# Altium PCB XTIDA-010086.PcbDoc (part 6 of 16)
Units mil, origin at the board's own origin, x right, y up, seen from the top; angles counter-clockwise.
Board outline 14763.78 x 8267.72 mil, 6 copper layers (Top Layer, GND Layer, Signal Layer 1, Signal Layer 2, Power Layer, Bottom Layer), stack 62 mil thick; 1933 components, 1002 nets, 4886 pads, 6482 vias.
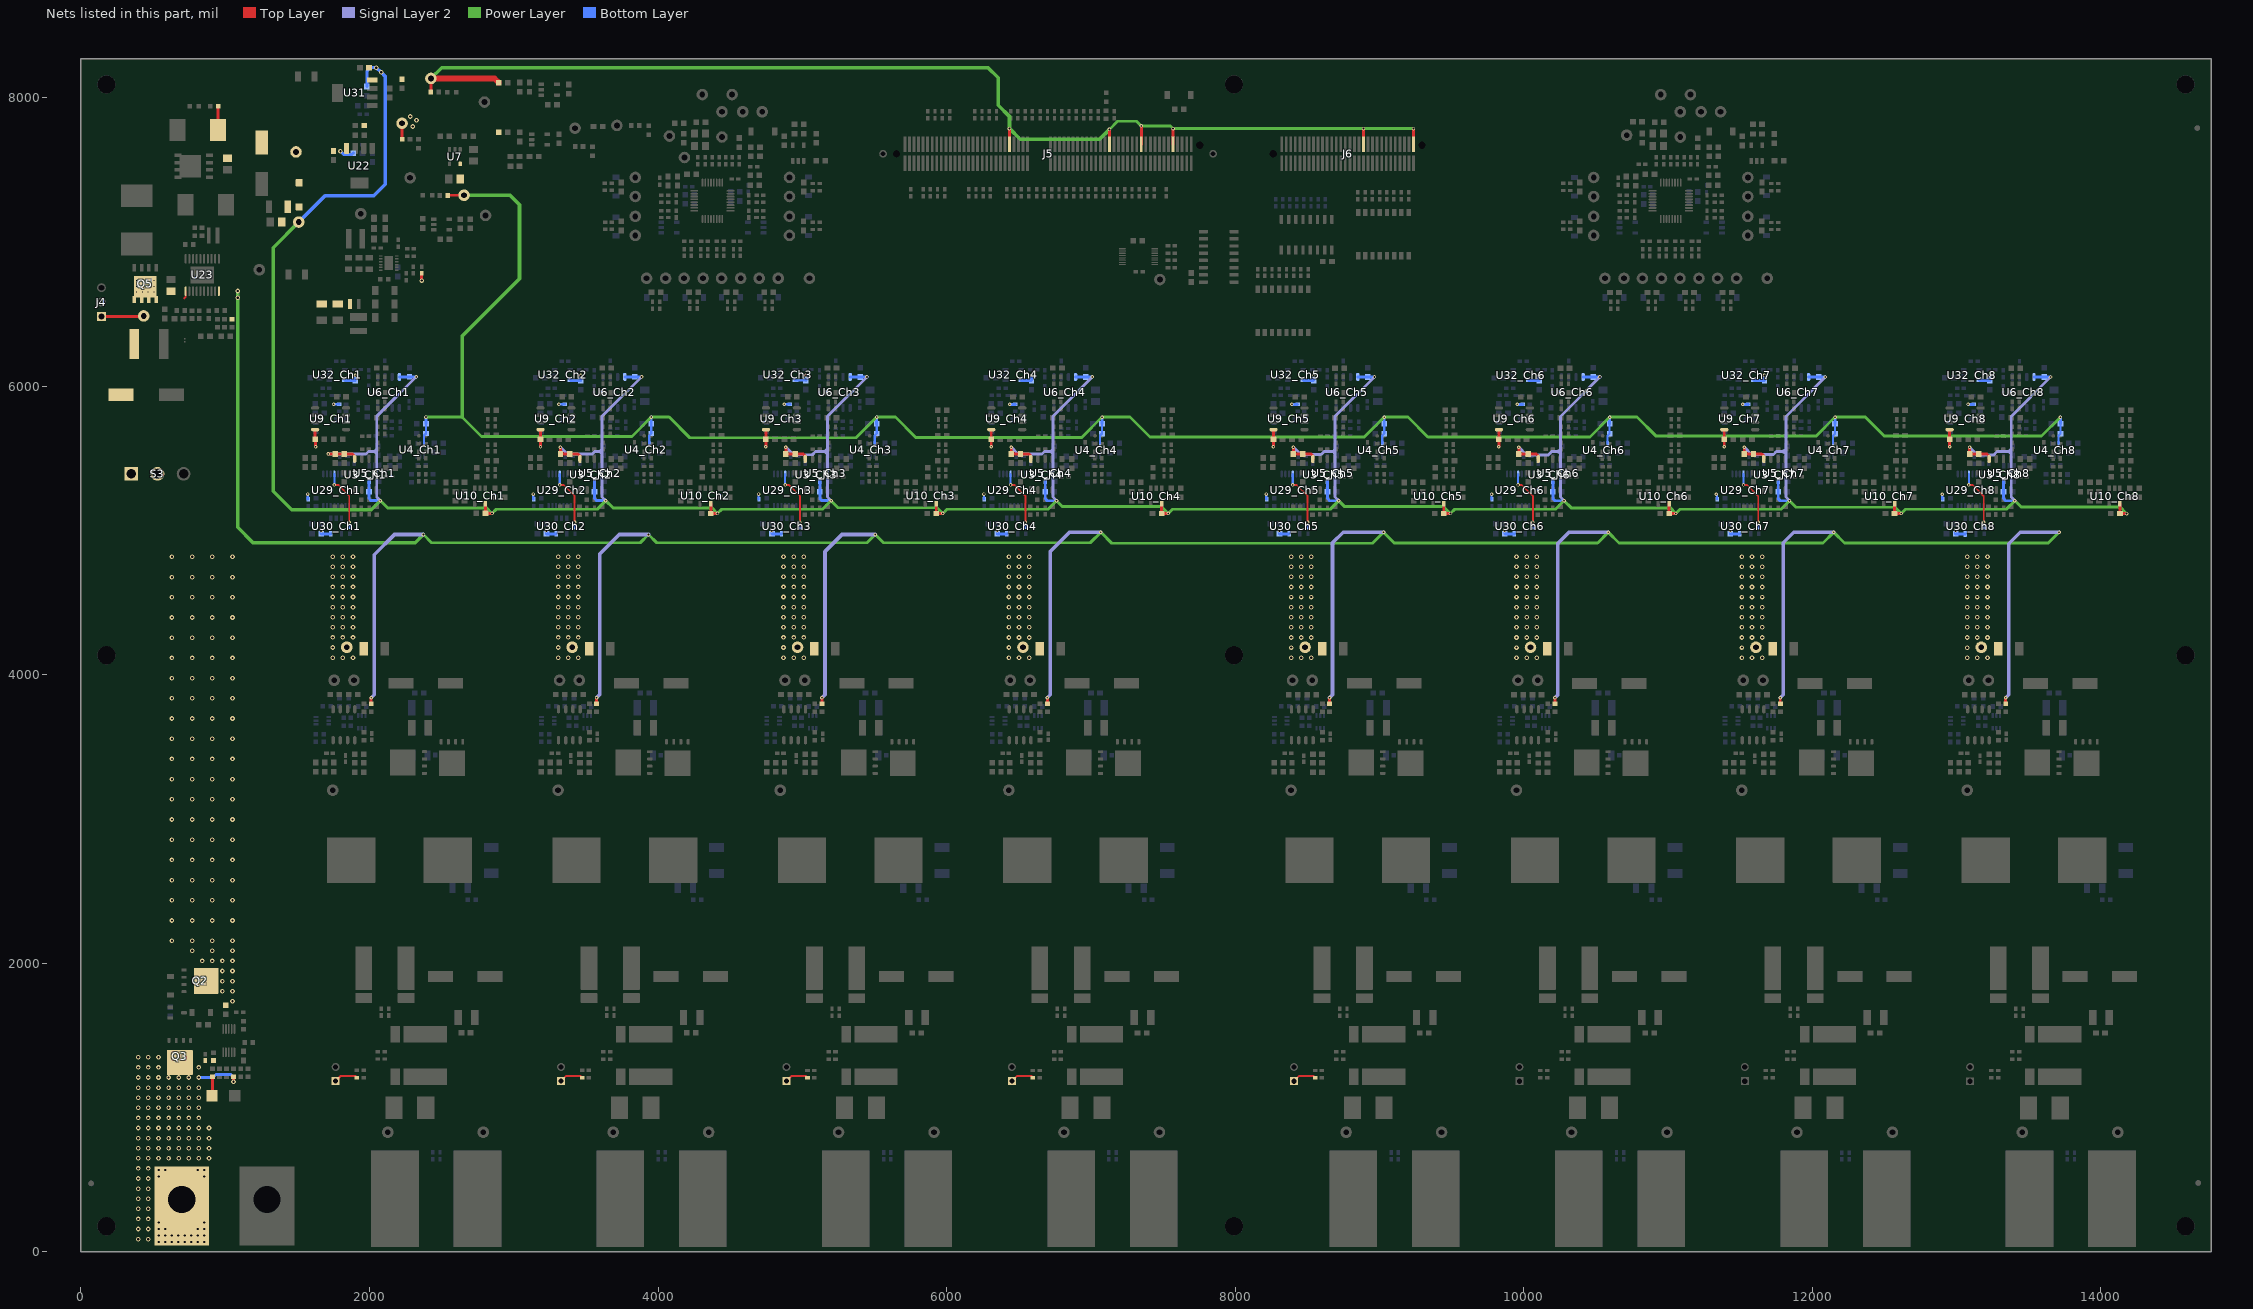
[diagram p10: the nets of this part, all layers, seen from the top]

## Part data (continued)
R10_Ch1 R10_Ch2 R10_Ch3 R10_Ch4 R10_Ch5 R10_Ch6 R10_Ch7 R10_Ch8 R12_Ch1 R12_Ch2 R12_Ch3 R12_Ch4 R12_Ch5 R12_Ch6 R12_Ch7 R12_Ch8 R13_Ch1 R13_Ch2 R13_Ch3 R13_Ch4 R13_Ch5 R13_Ch6 R13_Ch7 R13_Ch8 R14_Ch1 R14_Ch2 R14_Ch3 R14_Ch4 R14_Ch5 R14_Ch6 R14_Ch7 R14_Ch8 R15_Ch1 R15_Ch2 R15_Ch3 R15_Ch4 R15_Ch5 R15_Ch6 R15_Ch7 R15_Ch8 R16_Ch1 R16_Ch2 R16_Ch3 R16_Ch4 R16_Ch5 R16_Ch6 R16_Ch7 R16_Ch8 R17_Ch1 R17_Ch2 R17_Ch3 R17_Ch4 R17_Ch5 R17_Ch6 R17_Ch7 R17_Ch8 R20_Ch1 R20_Ch2 R20_Ch3 R20_Ch4 R20_Ch5 R20_Ch6 R20_Ch7 R20_Ch8 R28_Ch1 R28_Ch2 R28_Ch3 R28_Ch4 R28_Ch5 R28_Ch6 R28_Ch7 R28_Ch8 R29_Ch1 R29_Ch2 R29_Ch3 R29_Ch4 R29_Ch5 R29_Ch6 R29_Ch7 R29_Ch8 R31_Ch1 R31_Ch2 R31_Ch3 R31_Ch4 R31_Ch5 R31_Ch6 R31_Ch7 R31_Ch8 R32_Ch1 R32_Ch2 R32_Ch3 R32_Ch4 R32_Ch5 R32_Ch6 R32_Ch7 R32_Ch8 R41_Ch1 R41_Ch2 R41_Ch3 R41_Ch4 R41_Ch5 R41_Ch6 R41_Ch7 R41_Ch8 R43_Ch1 R43_Ch2 R43_Ch3 R43_Ch4 R43_Ch5 R43_Ch6 R43_Ch7 R43_Ch8 R45_Ch1 R45_Ch2 R45_Ch3 R45_Ch4 R45_Ch5 R45_Ch6 R45_Ch7 R45_Ch8 R47_Ch1 R47_Ch2 R47_Ch3 R47_Ch4 R47_Ch5 R47_Ch6 R47_Ch7 R47_Ch8 R48_Ch1 R48_Ch2 R48_Ch3 R48_Ch4 R48_Ch5 R48_Ch6 R48_Ch7 R48_Ch8 R49_Ch1 R49_Ch2 R49_Ch3 R49_Ch4 R49_Ch5 R49_Ch6 R49_Ch7 R49_Ch8 R54 R55 R56 R57 R58 R86 R90 R91 R92 R93 R94 R95 R96 R97 R99 R100 R101 R102 R103 R104 R105 R106 R107 R110 R111 R112 R113 R114 R115 R116 R117 R118 R119 R120 R121 R122 R123 R124 R125 R126 R127 R128 R130 R131 R132 R133 R134 R135 R136 R137 R138 R141 R142 R143 R144 R145 R146 R147 R148 R149 R150 R151 R159_Ch1 R159_Ch2 R159_Ch3 R159_Ch4 R159_Ch5 R159_Ch6 R159_Ch7 R159_Ch8 R160_Ch1 R160_Ch2 R160_Ch3 R160_Ch4 R160_Ch5 R160_Ch6 R160_Ch7 R160_Ch8 R161_Ch1 R161_Ch2 R161_Ch3 R161_Ch4 R161_Ch5 R161_Ch6 R161_Ch7 R161_Ch8 R164 R165 R166 R167 R168 R169 R170 R171 R175_Ch1 R175_Ch2 R175_Ch3 R175_Ch4 R175_Ch5 R175_Ch6 R175_Ch7 R175_Ch8 R185_Ch1 R185_Ch2 R185_Ch3 R185_Ch4 R185_Ch5 R185_Ch6 R185_Ch7 R185_Ch8 R186_Ch1 R186_Ch2 R186_Ch3 R186_Ch4 R186_Ch5 R186_Ch6 R186_Ch7 R186_Ch8 R187 R188 R189 R192_Ch1 R192_Ch2 R192_Ch3 R192_Ch4 R192_Ch5 R192_Ch6 R192_Ch7 R192_Ch8 R193_Ch1 R193_Ch2 R193_Ch3 R193_Ch4 R193_Ch5 R193_Ch6 R193_Ch7 R193_Ch8 R219_Ch1 R219_Ch2 R219_Ch3 R219_Ch4 R219_Ch5 R219_Ch6 R219_Ch7 R219_Ch8 R221 R245 R246 R247 R248 R249 R250 R251 R252 R253 R254 R255 R256 R257 R258 R259 R260 R261 R262 R263 R264 R265 R266 R267 R268 R269 R270 R271 R272 R273 R274 R275 R276 R278 R281 R283 R289 R293 R294 R295 R296 R297: "RES, 0, 5%, 0.063 W, 0402", Manufacturer=Vishay-Dale, Power_W=0.063, Supplier Part Number 1=541-0.0JCT-ND, TempCo="200 ppm/C", Tolerance_%=5, Value1=5%, Value2=0.063W, Value_Code=0000, ValueDisplayed=0
R11_Ch1 R11_Ch2 R11_Ch3 R11_Ch4 R11_Ch5 R11_Ch6 R11_Ch7 R11_Ch8 R21_Ch1 R21_Ch2 R21_Ch3 R21_Ch4 R21_Ch5 R21_Ch6 R21_Ch7 R21_Ch8: "RES, 2.00, 1%, 0.1 W, 0603", Manufacturer=Vishay-Dale, Power_W=0.1, Supplier Part Number 1=541-2.00HHCT-ND, TempCo="100 ppm/C", Tolerance_%=1, Value1=1%, Value2=0.1W, Value_Code=2R00, ValueDisplayed=2.00
R19_Ch1 R19_Ch2 R19_Ch3 R19_Ch4 R19_Ch5 R19_Ch6 R19_Ch7 R19_Ch8 R25_Ch1 R25_Ch2 R25_Ch3 R25_Ch4 R25_Ch5 R25_Ch6 R25_Ch7 R25_Ch8: library part CMP-0022900-4, "RES, 1.00, 1%, 0.1 W, 0603", Manufacturer=Yageo, Power_W=100mW, Supplier Part Number 1=311-1.00HRCT-ND, TempCo="200 ppm/C", Tolerance_%=1%, Value2=0.1W, Value_Code=1R00, ValueDisplayed=1
R22_Ch1 R22_Ch2 R22_Ch3 R22_Ch4 R22_Ch5 R22_Ch6 R22_Ch7 R22_Ch8 R23_Ch1 R23_Ch2 R23_Ch3 R23_Ch4 R23_Ch5 R23_Ch6 R23_Ch7 R23_Ch8 R26_Ch1 R26_Ch2 R26_Ch3 R26_Ch4 R26_Ch5 R26_Ch6 R26_Ch7 R26_Ch8 R27_Ch1 R27_Ch2 R27_Ch3 R27_Ch4 R27_Ch5 R27_Ch6 R27_Ch7 R27_Ch8 R42 R61_Ch1 R61_Ch2 R61_Ch3 R61_Ch4 R61_Ch5 R61_Ch6 R61_Ch7 R61_Ch8 R62_Ch1 R62_Ch2 R62_Ch3 R62_Ch4 R62_Ch5 R62_Ch6 R62_Ch7 R62_Ch8 R76_Ch1 R76_Ch2 R76_Ch3 R76_Ch4 R76_Ch5 R76_Ch6 R76_Ch7 R76_Ch8 R79_Ch1 R79_Ch2 R79_Ch3 R79_Ch4 R79_Ch5 R79_Ch6 R79_Ch7 R79_Ch8 R162_Ch1 R162_Ch2 R162_Ch3 R162_Ch4 R162_Ch5 R162_Ch6 R162_Ch7 R162_Ch8 R204_Ch1 R204_Ch2 R204_Ch3 R204_Ch4 R204_Ch5 R204_Ch6 R204_Ch7 R204_Ch8 R218_Ch1 R218_Ch2 R218_Ch3 R218_Ch4 R218_Ch5 R218_Ch6 R218_Ch7 R218_Ch8 R223 R224 R225 R226 R227 R228 R229 R230 R231 R232 R233 R234 R235 R236 R237 R238: "RES, 10.0 k, 1%, 0.063 W, 0402", Manufacturer=Vishay-Dale, Power_W=0.063, Supplier Part Number 1=541-10.0KLCT-ND, TempCo="100 ppm/C", Tolerance_%=1, Value1=1%, Value2=0.063W, Value_Code=10k0, ValueDisplayed=10.0k
R30_Ch1 R30_Ch2 R30_Ch3 R30_Ch4 R30_Ch5 R30_Ch6 R30_Ch7 R30_Ch8: library part CMP-0024060-1, "RES, 2.15 k, 0.1%, 0.1 W, 0603", Manufacturer="Yageo America", Power_W=100mW, TempCo="25 ppm/C", Tolerance_%=0.1%, Value2=0.1W, Value_Code=2k15, ValueDisplayed=2.15k
R33_Ch1 R33_Ch2 R33_Ch3 R33_Ch4 R33_Ch5 R33_Ch6 R33_Ch7 R33_Ch8 R34_Ch1 R34_Ch2 R34_Ch3 R34_Ch4 R34_Ch5 R34_Ch6 R34_Ch7 R34_Ch8 R35_Ch1 R35_Ch2 R35_Ch3 R35_Ch4 R35_Ch5 R35_Ch6 R35_Ch7 R35_Ch8 R36_Ch1 R36_Ch2 R36_Ch3 R36_Ch4 R36_Ch5 R36_Ch6 R36_Ch7 R36_Ch8 R37_Ch1 R37_Ch2 R37_Ch3 R37_Ch4 R37_Ch5 R37_Ch6 R37_Ch7 R37_Ch8 R38_Ch1 R38_Ch2 R38_Ch3 R38_Ch4 R38_Ch5 R38_Ch6 R38_Ch7 R38_Ch8 R39_Ch1 R39_Ch2 R39_Ch3 R39_Ch4 R39_Ch5 R39_Ch6 R39_Ch7 R39_Ch8 R40_Ch1 R40_Ch2 R40_Ch3 R40_Ch4 R40_Ch5 R40_Ch6 R40_Ch7 R40_Ch8 R65_Ch1 R65_Ch2 R65_Ch3 R65_Ch4 R65_Ch5 R65_Ch6 R65_Ch7 R65_Ch8 R66_Ch1 R66_Ch2 R66_Ch3 R66_Ch4 R66_Ch5 R66_Ch6 R66_Ch7 R66_Ch8 R67_Ch1 R67_Ch2 R67_Ch3 R67_Ch4 R67_Ch5 R67_Ch6 R67_Ch7 R67_Ch8 R68_Ch1 R68_Ch2 R68_Ch3 R68_Ch4 R68_Ch5 R68_Ch6 R68_Ch7 R68_Ch8 R71_Ch1 R71_Ch2 R71_Ch3 R71_Ch4 R71_Ch5 R71_Ch6 R71_Ch7 R71_Ch8 R72_Ch1 R72_Ch2 R72_Ch3 R72_Ch4 R72_Ch5 R72_Ch6 R72_Ch7 R72_Ch8 R73_Ch1 R73_Ch2 R73_Ch3 R73_Ch4 R73_Ch5 R73_Ch6 R73_Ch7 R73_Ch8 R74_Ch1 R74_Ch2 R74_Ch3 R74_Ch4 R74_Ch5 R74_Ch6 R74_Ch7 R74_Ch8: "RES, 500, 0.1%, 0.05 W, 0402", Manufacturer="Vishay Thin Film", Power_W=0.05, Supplier Part Number 1=541-1905-1-ND, TempCo="25 ppm/C", Tolerance_%=0.1, Value1=0.1%, Value2=0.05W, Value_Code=500R, ValueDisplayed=500
R44_Ch1 R44_Ch2 R44_Ch3 R44_Ch4 R44_Ch5 R44_Ch6 R44_Ch7 R44_Ch8: "RES, 2.00 k, 0.1%, 0.1 W, 0603", Manufacturer="Yageo America", Power_W=0.1, Supplier Part Number 1=603-RT0603BRD072KL, TempCo="25 ppm/C", Value1=0.1%, Value2=0.1W, Value_Code=2k00, ValueDisplayed=2.00k
R46_Ch1 R46_Ch2 R46_Ch3 R46_Ch4 R46_Ch5 R46_Ch6 R46_Ch7 R46_Ch8: "RES, 7.96 k, 0.1%, 0.1 W, 0603", Manufacturer="Yageo America", Power_W=0.1, TempCo="25 ppm/C", Value1=0.1%, Value2=0.1W, Value_Code=7k96, ValueDisplayed=7.96k
R50_Ch1 R50_Ch2 R50_Ch3 R50_Ch4 R50_Ch5 R50_Ch6 R50_Ch7 R50_Ch8: "RES, 2.7 k, 5%, 0.063 W, 0402", Manufacturer=Vishay-Dale, Power_W=0.063, Supplier Part Number 1=541-2.7KJCT-ND, TempCo="200 ppm/C", Tolerance_%=5, Value1=5%, Value2=0.063W, Value_Code=2k70, ValueDisplayed=2.7k
R51_Ch1 R51_Ch2 R51_Ch3 R51_Ch4 R51_Ch5 R51_Ch6 R51_Ch7 R51_Ch8: "RES, 5.1 k, 5%, 0.063 W, 0402", Manufacturer=Vishay-Dale, Power_W=0.063, Supplier Part Number 1=541-5.1KJCT-ND, TempCo="200 ppm/C", Tolerance_%=5, Value1=5%, Value2=0.063W, Value_Code=5k10, ValueDisplayed=5.1k
R52_Ch1 R52_Ch2 R52_Ch3 R52_Ch4 R52_Ch5 R52_Ch6 R52_Ch7 R52_Ch8: "RES, 7.50 k, 1%, 0.063 W, 0402", Manufacturer=Vishay-Dale, Power_W=0.063, Supplier Part Number 1=541-7.50KLCT-ND, TempCo="100 ppm/C", Tolerance_%=1, Value1=1%, Value2=0.063W, Value_Code=7k50, ValueDisplayed=7.50k
R53_Ch1 R53_Ch2 R53_Ch3 R53_Ch4 R53_Ch5 R53_Ch6 R53_Ch7 R53_Ch8: "RES, 11.0 k, 1%, 0.063 W, 0402", Manufacturer=Vishay-Dale, Power_W=0.063, Supplier Part Number 1=541-11.0KLCT-ND, TempCo="100 ppm/C", Tolerance_%=1, Value1=1%, Value2=0.063W, Value_Code=11k0, ValueDisplayed=11.0k
R59 R178 R179 R180 R182 R183 R209: "RES, 4.99 k, 1%, 0.1 W, 0603", Manufacturer=Vishay-Dale, Power_W=0.1, Supplier Part Number 1=541-4.99KHCT-ND, TempCo="100 ppm/C", Tolerance_%=1, Value1=1%, Value2=0.1W, Value_Code=4k99, ValueDisplayed=4.99k
R63_Ch1 R63_Ch2 R63_Ch3 R63_Ch4 R63_Ch5 R63_Ch6 R63_Ch7 R63_Ch8 R77_Ch1 R77_Ch2 R77_Ch3 R77_Ch4 R77_Ch5 R77_Ch6 R77_Ch7 R77_Ch8: library part CMP-0023991-3, "RES, 24.0 k, 0.1%, 0.1 W, 0603", Manufacturer="Yageo America", Power_W=100mW, TempCo="25 ppm/C", Tolerance_%=0.1%, Value2=0.1W, Value_Code=24k0, ValueDisplayed=24.0k
R64_Ch1 R64_Ch2 R64_Ch3 R64_Ch4 R64_Ch5 R64_Ch6 R64_Ch7 R64_Ch8 R70_Ch1 R70_Ch2 R70_Ch3 R70_Ch4 R70_Ch5 R70_Ch6 R70_Ch7 R70_Ch8: library part CMP-0023630-3, "RES, 100 k, 0.1%, 0.1 W, 0603", Manufacturer="Yageo America", Power_W=100mW, Supplier Part Number 1=603-RT0603BRD07100KL, TempCo="25 ppm/C", Tolerance_%=0.1%, Value2=0.1W, Value_Code=100k
R69_Ch1 R69_Ch2 R69_Ch3 R69_Ch4 R69_Ch5 R69_Ch6 R69_Ch7 R69_Ch8: "RES, 3.32 k, 1%, 0.1 W, 0603", Manufacturer=Vishay-Dale, Power_W=0.1, Supplier Part Number 1=541-3.32KHCT-ND, TempCo="100 ppm/C", Tolerance_%=1, Value1=1%, Value2=0.1W, Value_Code=3k32, ValueDisplayed=3.32k
R75_Ch1 R75_Ch2 R75_Ch3 R75_Ch4 R75_Ch5 R75_Ch6 R75_Ch7 R75_Ch8 R78_Ch1 R78_Ch2 R78_Ch3 R78_Ch4 R78_Ch5 R78_Ch6 R78_Ch7 R78_Ch8: "RES, 10.0 k, 1%, 0.1 W, 0603", Manufacturer=Vishay-Dale, Power_W=0.1, Supplier Part Number 1=541-10.0KHCT-ND, TempCo="100 ppm/C", Tolerance_%=1, Value1=1%, Value2=0.1W, Value_Code=10k0, ValueDisplayed=10.0k
R80: "RES, 2.00 k, 1%, 0.1 W, 0603", Manufacturer=Vishay-Dale, Power_W=0.1, Supplier Part Number 1=541-2.00KHCT-ND, TempCo="100 ppm/C", Tolerance_%=1, Value1=1%, Value2=0.1W, Value_Code=2k00, ValueDisplayed=2.00k
R81: "RES, 330 k, 1%, 0.1 W, 0603", Manufacturer="Yageo America", Power_W=0.1, Supplier Part Number 1=311-330KHRCT-ND, TempCo="200 ppm/C", Tolerance_%=1, Value1=1%, Value2=0.1W, Value_Code=330k
R82 R88 R89: "RES, 10.0 k, 1%, 0.1 W, 0603", Manufacturer="Yageo America", Power_W=0.1, Supplier Part Number 1=311-10.0KHRCT-ND, TempCo="200 ppm/C", Tolerance_%=1, Value1=1%, Value2=0.1W, Value_Code=10k0, ValueDisplayed=10.0k
R83: "RES, 20.5 k, 1%, 0.1 W, 0603", Manufacturer=Vishay-Dale, Power_W=0.1, Supplier Part Number 1=541-20.5KHCT-ND, TempCo="100 ppm/C", Tolerance_%=1, Value1=1%, Value2=0.1W, Value_Code=20k5, ValueDisplayed=20.5k
R84: "RES, 54.9 k, 1%, 0.1 W, 0603", Manufacturer="Yageo America", Power_W=0.1, Supplier Part Number 1=311-54.9KHRCT-ND, TempCo="200 ppm/C", Tolerance_%=1, Value1=1%, Value2=0.1W, Value_Code=54k9, ValueDisplayed=54.9k
R85: "RES, 62.0 k, 1%, 0.1 W, 0603", Manufacturer="Yageo America", Power_W=0.1, Supplier Part Number 1=311-62.0KHRCT-ND, TempCo="200 ppm/C", Tolerance_%=1, Value1=1%, Value2=0.1W, Value_Code=62k0, ValueDisplayed=62.0k
R87: "RES, 1.00 M, 1%, 0.1 W, 0603", Manufacturer=Vishay-Dale, Power_W=0.1, Supplier Part Number 1=541-1.00MHCT-ND, TempCo="100 ppm/C", Tolerance_%=1, Value1=1%, Value2=0.1W, Value_Code=1M00, ValueDisplayed=1.00M
R98 R108 R109 R129 R139 R140 R177 R181: library part CMP-0022735-5, "RES, 100 k, 1%, 0.1 W, 0603", Manufacturer=Yageo, Power_W=100mW, Supplier Part Number 1=311-100KHRCT-ND, TempCo="100 ppm/C", Tolerance_%=1%, Value2=0.1W, Value_Code=100k
R152 R153: "RES, 0, 1%, 0.5 W, 1206", Manufacturer=Keystone, Power_W=0.5, Supplier Part Number 1=36-5108CT-ND, TempCo=ppm/C, Tolerance_%=1, Value1=1%, Value2=0.5W, Value_Code=0
R163 R176 R201 R203 R205: library part CMP-0025874-3, "RES, 0, 5%, 0.1 W, 0603", Manufacturer=Panasonic, PartNumber=ERJ-3GEY0R00V, Power_W=100mW, Supplier Part Number 1=P0.0GCT-ND, TempCo="600 ppm/C", Tolerance_%=5%, Value2=0.1W, Value_Code=0000, ValueDisplayed=0
R184 R202: library part CMP-0021990-1, "RES, 100 k, 1%, 0.1 W, 0603", Manufacturer=Vishay-Dale, Power_W=100mW, Supplier Part Number 1=541-100KHCT-ND, TempCo="100 ppm/C", Tolerance_%=1%, Value2=0.1W, Value_Code=100k
R196: "RES, 49.9, 1%, 0.063 W, 0402", Manufacturer=Vishay-Dale, Power_W=0.063, Supplier Part Number 1=541-49.9LCT-ND, TempCo="100 ppm/C", Tolerance_%=1, Value1=1%, Value2=0.063W, Value_Code=49R9, ValueDisplayed=49.9
R197: "RES, 130 k, 1%, 0.063 W, 0402", Manufacturer=Vishay-Dale, Power_W=0.063, Supplier Part Number 1=541-130KLCT-ND, TempCo="100 ppm/C", Tolerance_%=1, Value1=1%, Value2=0.063W, Value_Code=130k
R198 R200: "RES, 100 k, 0.5%, 0.063 W, 0402", Manufacturer=Vishay-Dale, Power_W=0.063, Supplier Part Number 1=541-100KAVCT-ND, TempCo="50 ppm/C", Tolerance_%=0.5, Value1=0.5%, Value2=0.063W, Value_Code=100k
R199: "RES, 24 k, 5%, 0.063 W, 0402", Manufacturer=Vishay-Dale, Power_W=0.063, Supplier Part Number 1=541-24KJCT-ND, TempCo="200 ppm/C", Tolerance_%=5, Value1=5%, Value2=0.063W, Value_Code=24k0, ValueDisplayed=24k
R206: "RES, 20.0 k, 1%, 0.1 W, 0603", Manufacturer=Vishay-Dale, Power_W=0.1, Supplier Part Number 1=541-20.0KHCT-ND, TempCo="100 ppm/C", Tolerance_%=1, Value1=1%, Value2=0.1W, Value_Code=20k0, ValueDisplayed=20.0k
R207: "RES, 100 k, 1%, 0.1 W, 0603", Manufacturer="Yageo America", Power_W=0.1, Supplier Part Number 1=311-100KHRCT-ND, TempCo="200 ppm/C", Tolerance_%=1, Value1=1%, Value2=0.1W, Value_Code=100k
R208: "RES, 49.9 k, 1%, 0.1 W, 0603", Manufacturer=Vishay-Dale, Power_W=0.1, Supplier Part Number 1=541-49.9KHCT-ND, TempCo="100 ppm/C", Tolerance_%=1, Value1=1%, Value2=0.1W, Value_Code=49k9, ValueDisplayed=49.9k
R210: "RES, 18.2 k, 1%, 0.1 W, 0603", Manufacturer=Vishay-Dale, Power_W=0.1, Supplier Part Number 1=541-18.2KHCT-ND, TempCo="100 ppm/C", Tolerance_%=1, Value1=1%, Value2=0.1W, Value_Code=18k2, ValueDisplayed=18.2k
R211: "RES, 0.068, 1%, 1 W, 0612", Manufacturer="Susumu Co Ltd", Power_W=1, Supplier Part Number 1=PRL1632.068FCT-ND, TempCo="50 ppm/C", Value1=1%, Value2=1W, Value_Code=R068, ValueDisplayed=0.068
R212: "RES, 24.0 k, 1%, 0.1 W, 0603", Manufacturer="Yageo America", Power_W=0.1, Supplier Part Number 1=311-24.0KHRCT-ND, TempCo="200 ppm/C", Tolerance_%=1, Value1=1%, Value2=0.1W, Value_Code=24k0, ValueDisplayed=24.0k
R213: library part CMP-0023278-3, "RES, 7.32 k, 1%, 0.1 W, 0603", Manufacturer="Yageo America", Power_W=100mW, Supplier Part Number 1=311-7.32KHRCT-ND, TempCo="200 ppm/C", Tolerance_%=1%, Value2=0.1W, Value_Code=7k32, ValueDisplayed=7.32k
R214: library part CMP-0023172-3, "RES, 52.3 k, 1%, 0.1 W, 0603", Manufacturer="Yageo America", Power_W=100mW, Supplier Part Number 1=311-52.3KHRCT-ND, TempCo="200 ppm/C", Tolerance_%=1%, Value2=0.1W, Value_Code=52k3, ValueDisplayed=52.3k
R215: "RES, 10.0, 1%, 0.1 W, 0603", Manufacturer=Vishay-Dale, Power_W=0.1, Supplier Part Number 1=541-10.0HCT-ND, TempCo="100 ppm/C", Tolerance_%=1, Value1=1%, Value2=0.1W, Value_Code=10R0, ValueDisplayed=10.0
R277 R279 R280 R282 R284 R285 R286 R288 R292 R298: "RES, 50, 0.1%, 0.05 W, 0402", Manufacturer=Vishay-Dale, Power_W=0.05, Supplier Part Number 1=FC0402-50BWCT-ND, TempCo="25 ppm/C", Tolerance_%=0.1, Value1=0.1%, Value2=0.05W, Value_Code=50R0, ValueDisplayed=50
S1 S2 S6: library part CMP-0002143-3, "Switch, Tactile, SPST-NO, 0.05A, 12V, SMT", CurrentRating_mA=50A, Manufacturer=E-Switch, PartNumber=TL1015AF160QG, Supplier Part Number 1=EG4344CT-ND
S3: "SWITCH SLIDE SPST 4A PCB, TH", CurrentRating_mA=4000, Manufacturer="C&K Components", Supplier Part Number 1=CKC5106-ND
S4 S5: library part CMP-0002229-1, "Switch, SPST, 8 Pos, 25mA, 24VDC, SMD", CurrentRating_mA=25A, Manufacturer="CTS Electrocomponents", Supplier Part Number 1=CT2188LPST-ND
SH-J4: "Shunt, 2.54mm, Gold, Black", Manufacturer="Wurth Elektronik", Supplier Part Number 1=732-2678-ND
T1 T2: "Terminal 50A Lug", Manufacturer=Panduit, Supplier Part Number 1=CB35-36-CY-ND, Voltage_V=600
TP1_Ch1 TP1_Ch2 TP1_Ch3 TP1_Ch4 TP1_Ch5 TP1_Ch6 TP1_Ch7 TP1_Ch8 TP3_Ch1 TP3_Ch2 TP3_Ch3 TP3_Ch4 TP3_Ch5 TP3_Ch6 TP3_Ch7 TP3_Ch8 TP7_Ch1 TP7_Ch2 TP7_Ch3 TP7_Ch4 TP7_Ch5 TP7_Ch6 TP7_Ch7 TP7_Ch8 TP8_Ch1 TP8_Ch2 TP8_Ch3 TP8_Ch4 TP8_Ch5 TP8_Ch6 TP8_Ch7 TP8_Ch8 TP9_Ch1 TP9_Ch2 TP9_Ch3 TP9_Ch4 TP9_Ch5 TP9_Ch6 TP9_Ch7 TP9_Ch8 TP10_Ch1 TP10_Ch2 TP10_Ch3 TP10_Ch4 TP10_Ch5 TP10_Ch6 TP10_Ch7 TP10_Ch8 TP11 TP12 TP13 TP14 TP15 TP16 TP17 TP18 TP19 TP20 TP21 TP22 TP23: "Test Point, Miniature, White, TH", Color=White, Manufacturer=Keystone, Supplier Part Number 1=36-5002-ND
TP2_Ch1 TP2_Ch2 TP2_Ch3 TP2_Ch4 TP2_Ch5 TP2_Ch6 TP2_Ch7 TP2_Ch8 TP4_Ch1 TP4_Ch2 TP4_Ch3 TP4_Ch4 TP4_Ch5 TP4_Ch6 TP4_Ch7 TP4_Ch8 TP5_Ch1 TP5_Ch2 TP5_Ch3 TP5_Ch4 TP5_Ch5 TP5_Ch6 TP5_Ch7 TP5_Ch8 TP24 TP25 TP26 TP27 TP28 TP29 TP30 TP31 TP32 TP33: "Test Point, Miniature, Red, TH", Color=Red, Manufacturer=Keystone, Supplier Part Number 1=36-5000-ND
TP6_Ch1 TP6_Ch2 TP6_Ch3 TP6_Ch4 TP6_Ch5 TP6_Ch6 TP6_Ch7 TP6_Ch8 TP34 TP35 TP36 TP37 TP38 TP39 TP40 TP41: "Test Point, Miniature, Black, TH", Color=Black, Manufacturer=Keystone, Supplier Part Number 1=36-5001-ND
U1_Ch1 U1_Ch2 U1_Ch3 U1_Ch4 U1_Ch5 U1_Ch6 U1_Ch7 U1_Ch8: library part CMP-0071433-1, "High Voltage 1A Peak Half Bridge Gate Driver, 8-pin Narrow SOIC, Pb-Free", Manufacturer="Texas Instruments", PackageTopMarking=NSZXTT*L5109*BMA, PowerWise=N
U2_Ch1 U2_Ch2 U2_Ch3 U2_Ch4 U2_Ch5 U2_Ch6 U2_Ch7 U2_Ch8 U24_Ch1 U24_Ch2 U24_Ch3 U24_Ch4 U24_Ch5 U24_Ch6 U24_Ch7 U24_Ch8: library part CMP-0051216-2, "Single 3-Input Positive-AND Gate, DCK0006A, LARGE T&R", F @ Nom Voltage(Max)(Mhz)=150, Generic Part Number=SN74LVC1G11, ICC @ Nom Voltage(Max)(mA)=0.01, Manufacturer="Texas Instruments", Operating Temperature Range(C)="-40 to 125,-40 to 85", Rating=Catalog, tpd @ Nom Voltage(Max)(ns)=20,7.8,6.2,4.6, Voltage(Nom)(V)=1.8,2.5,3.3,5
U3_Ch1 U3_Ch2 U3_Ch3 U3_Ch4 U3_Ch5 U3_Ch6 U3_Ch7 U3_Ch8: library part CMP-0860958-1, "4.7MHz, 35µV offset, 7nV/vHz noise, low-power, super beta precision instrumentation amplifier, D0008A (SOIC-8)", Alternate Manufacturer="Texas Instruments", Operating Temperature Range="-40 to 125 C", Rating=Catalog
U4_Ch1 U4_Ch2 U4_Ch3 U4_Ch4 U4_Ch5 U4_Ch6 U4_Ch7 U4_Ch8: library part CMP-0065137-4, "Low Supply, Voltage Output, Low- or High-Side Measurement, Bidirectional, Zero-Drift Series, Current-Shunt Monitor, DCK0006A (SOT-SC70-6)", Alternate Manufacturer="Texas Instruments"
U5_Ch1 U5_Ch2 U5_Ch3 U5_Ch4 U5_Ch5 U5_Ch6 U5_Ch7 U5_Ch8 U10_Ch1 U10_Ch2 U10_Ch3 U10_Ch4 U10_Ch5 U10_Ch6 U10_Ch7 U10_Ch8 U32_Ch1 U32_Ch2 U32_Ch3 U32_Ch4 U32_Ch5 U32_Ch6 U32_Ch7 U32_Ch8: library part CMP-0073526-1, "36V, Low-Power, RRO, General-Purpose Operational Amplifier, DBV0005A (SOT-23-5)", Alternate Manufacturer="Texas Instruments", Alternate PartNumber=TLV171IDBVT
U6_Ch1 U6_Ch2 U6_Ch3 U6_Ch4 U6_Ch5 U6_Ch6 U6_Ch7 U6_Ch8: library part CMP-0073529-1, "36V, Low Power, RRO, General Purpose Operational Amplifier, D0008A (SOIC-8)", Alternate Manufacturer="Texas Instruments"
U7: library part CMP-0076238-1, "250-mA Ultra-Low-Noise, Low-IQ LDO, DBV0005A (SOT-23-5)", Alternate Manufacturer="Texas Instruments"
U8: "Single Output High PSRR LDO, 200 mA, Fixed -2.5 V Output, -10 to -2.7 V Input, 5-pin SOT-23 (DBV), -40 to 125 degC, Green (RoHS & no Sb/Br)", Alternate Manufacturer="Texas Instruments", Alternate PartNumber=Equivalent, Supplier Part Number 1=296-15799-1-ND
U9_Ch1 U9_Ch2 U9_Ch3 U9_Ch4 U9_Ch5 U9_Ch6 U9_Ch7 U9_Ch8: "Dual Comparator, D0008A", Alternate Manufacturer="Texas Instruments"
U11: library part LM5060Q1MMX/NOPB, "High-Side Protection Controller with Low Quiescent Current, 10-pin MSOP, Pb-Free", Manufacturer="Texas Instruments", PackageTopMarking=ZXTT*SZAB, PowerWise=N
U12 U16: library part CMP-0085527-1, "8-Channel, 24-Bit, Simultaneously-Sampling, Delta-Sigma ADC, PBS0032A (TQFP-32)", Alternate Manufacturer="Texas Instruments"
U13 U14 U17 U18: library part CMP-0085633-1, "3.6V Data-Line Surge and 30kV ESD Protection Diode Array, DBV0005A (SOT-23-5)", Alternate Manufacturer="Texas Instruments", Operating Temperature Range="-40 to 125 C", Rating=Catalog
U15 U19: library part CMP-0013048-2, "DUAL OUTPUT VOLTAGE REFERENCE 2.5V, DBV0005A (SOT-5)", Alternate Manufacturer="Texas Instruments"
U20: library part CMP-0066020-1, "250-mA Ultra-Low-Noise, Low-IQ LDO, DBV0005A (SOT-23-5)", Alternate Manufacturer="Texas Instruments"
U21: "Synchronous Inverting Buck Converter, DRR0012C", Alternate Manufacturer="Texas Instruments"
U22 U31: library part CMP-0070852-1, "500mA Low Dropout CMOS Linear Regulators Stable with Ceramic Output Capacitors, 5-pin SOT-223, Pb-Free, 1000 Reel", Manufacturer="Texas Instruments", PackageTopMarking=XYTT*LJZB, PowerWise=Y
U23: "Wide Voltage Range Buck-Boost Controller, 20-pin TSSOP-EP, Pb-Free", Manufacturer="Texas Instruments", PackageTopMarking=NSUZXYTT*LM5118*MH, PowerWise=Y, Supplier Part Number 1=LM5118MH-ND
U25: library part CMP-0036866-2, "Single Output Low Noise LDO, 400 mA, Fixed 3.3 V Output, 1.7 to 5.5 V Input, with Reverse Current Protection, 5-pin SOT-23 (DBV), -40 to 85 degC, Green (RoHS & no Sb/Br)", Alternate Manufacturer="Texas Instruments", Alternate PartNumber=TPS73633DBVT, Rating=Catalog
U26 U27: library part CMP-0088185-1, "Priority Encoder 1 x 8:3 16-SOIC", Manufacturer="Texas Instruments", Operating Temperature Range="-40°C to +85°C"
U28: library part CMP-0076579-1, "4-BIT SYNCHRONOUS BINARY COUNTER, DGV0016A (TVSOP-16)", Alternate Manufacturer="Texas Instruments"
U29_Ch1 U29_Ch2 U29_Ch3 U29_Ch4 U29_Ch5 U29_Ch6 U29_Ch7 U29_Ch8: library part CMP-0076523-1, "CMOS Triple 2-Channel Analog Multiplexer/Demultiplexer with Logic-Level Conversion, PW0016A (TSSOP-16)", Alternate Manufacturer="Texas Instruments", Alternate PartNumber=CD4053BPW
U30_Ch1 U30_Ch2 U30_Ch3 U30_Ch4 U30_Ch5 U30_Ch6 U30_Ch7 U30_Ch8: library part CMP-0073515-1, "2.2-V to 36-V, microPower Comparator, DBV0005A (SOT-23-5)", Alternate Manufacturer="Texas Instruments", Alternate PartNumber=TLV1701AIDBVT
Y1 Y2: library part CMP-0081928-1, "Oscillator, 8.192 MHz, 15 pF, AEC-Q200 Grade 1, SMD", Frequency_Fixed=8.192MHz, Frequency Stability="25 ppm", Load Capacitance="15 pF", Manufacturer=SiTime, Supplier Part Number 1=1473-1658-1-ND
ZZ1: library part CMP-0003616-3
ZZ2: library part CMP-0077236-1
ZZ3: library part CMP-0077237-1
ZZ4: library part CMP-0077238-1

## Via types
v1: diameter 32, hole 16, Top Layer to Bottom Layer, tented both sides, 4685 vias
v2: diameter 24, hole 12, Top Layer to Bottom Layer, tented both sides, 1013 vias
v3: diameter 32, hole 16, Top Layer to Bottom Layer, 728 vias
v4: diameter 19.68, hole 7.87, Top Layer to Bottom Layer, 40 vias
v5: diameter 214.57, hole 140, Top Layer to Bottom Layer, 16 vias

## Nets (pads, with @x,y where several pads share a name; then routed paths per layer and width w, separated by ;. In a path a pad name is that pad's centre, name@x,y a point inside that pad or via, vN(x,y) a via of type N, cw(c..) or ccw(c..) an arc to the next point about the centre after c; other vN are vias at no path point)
2P5V: C30_Ch1.1 C30_Ch2.1 C30_Ch3.1 C30_Ch4.1 C30_Ch5.1 C30_Ch6.1 C30_Ch7.1 C30_Ch8.1 C31_Ch1.1 C31_Ch2.1 C31_Ch3.1 C31_Ch4.1 C31_Ch5.1 C31_Ch6.1 C31_Ch7.1 C31_Ch8.1 C130.1 R178.1 TP31.1 U4_Ch1.3 U4_Ch2.3 U4_Ch3.3 U4_Ch4.3 U4_Ch5.3 U4_Ch6.3 U4_Ch7.3 U4_Ch8.3 U7.5 | length 15795.1
  Top Layer w20: R178.1@2542.56,7321.32 2543.56,7322.32 TP31.1@2656,7322.32
  Power Layer w20: v2(2391.5,5784.99) 2642.01,5784.99 2776,5651 3819.58,5651 v2(3953.5,5784.91) 4077.32,5784.91 4220.23,5642 5372.66,5642 v2(5515.5,5784.83) 5645.17,5784.83 5786,5644 6936.74,5644 v2(7077.5,5784.76) 7270.24,5784.76 7409,5646 8894.52,5646 v2(9033.2,5784.68) 9198.32,5784.68 9335,5648 10458.6,5648 v2(10595.2,5784.6) 10785.4,5784.6 10915,5655 12027.68,5655 v2(12157.2,5784.52) 12366.48,5784.52 12498,5653 13587.76,5653 v2(13719.2,5784.44)
  Power Layer w25: 2642.01,5784.99 2642.01,6345.01 3040,6743 3040,7257 2974.68,7322.32 TP31.1@2656,7322.32
  Bottom Layer w15: U4_Ch1.3@2377.59,5601.34 2377.59,5657.14 C30_Ch1.1@2391.5,5671.05 C31_Ch1.1@2391.5,5738.05 ; U4_Ch2.3@3939.59,5601.26 3939.59,5657.06 C30_Ch2.1@3953.5,5670.97 C31_Ch2.1@3953.5,5737.97 ; U4_Ch3.3@5501.59,5601.18 5501.59,5656.98 C30_Ch3.1@5515.5,5670.89 C31_Ch3.1@5515.5,5737.89 ; U4_Ch4.3@7063.59,5601.1 7063.59,5656.91 C30_Ch4.1@7077.5,5670.81 C31_Ch4.1@7077.5,5737.81 ; U4_Ch5.3@9019.29,5601.02 9019.29,5656.83 C30_Ch5.1@9033.2,5670.73 C31_Ch5.1@9033.2,5737.73 ; U4_Ch6.3@10581.29,5600.94 10581.29,5656.75 C30_Ch6.1@10595.2,5670.65 C31_Ch6.1@10595.2,5737.65 ; U4_Ch7.3@12143.29,5600.87 12143.29,5656.67 C30_Ch7.1@12157.2,5670.57 C31_Ch7.1@12157.2,5737.57 ; U4_Ch8.3@13705.29,5600.79 13705.29,5656.59 C30_Ch8.1@13719.2,5670.5 C31_Ch8.1@13719.2,5737.5
  Bottom Layer w20: C31_Ch1.1@2391.5,5738.05 v2(2391.5,5784.99) ; C31_Ch2.1@3953.5,5737.97 v2(3953.5,5784.91) ; C31_Ch3.1@5515.5,5737.89 v2(5515.5,5784.83) ; C31_Ch4.1@7077.5,5737.81 v2(7077.5,5784.76) ; C31_Ch5.1@9033.2,5737.73 v2(9033.2,5784.68) ; C31_Ch6.1@10595.2,5737.65 v2(10595.2,5784.6) ; C31_Ch7.1@12157.2,5737.57 v2(12157.2,5784.52) ; C31_Ch8.1@13719.2,5737.5 v2(13719.2,5784.44)
3-COM_Ch1: R160_Ch1.2 U29_Ch1.4 | length 426.8
  Top Layer w12: v2(1757,5315) 1783,5315 1860,5238 v2(1860,5057)
  Bottom Layer w12: v2(1860,5057) 1860,5026.62 R160_Ch1.2@1863,5023.62
  Bottom Layer w15: v2(1757,5315) 1757,5391 U29_Ch1.4@1757.2,5391.2
3-COM_Ch2: R160_Ch2.2 U29_Ch2.4 | length 426.8
  Top Layer w12: v2(3319,5314.92) 3345,5314.92 3422,5237.92 v2(3422,5056.92)
  Bottom Layer w12: v2(3422,5056.92) 3422,5026.54 R160_Ch2.2@3425,5023.54
  Bottom Layer w15: v2(3319,5314.92) 3319,5390.92 U29_Ch2.4@3319.2,5391.13
3-COM_Ch3: R160_Ch3.2 U29_Ch3.4 | length 426.8
  Top Layer w12: v2(4881,5314.84) 4907,5314.84 4984,5237.84 v2(4984,5056.84)
  Bottom Layer w12: v2(4984,5056.84) 4984,5026.46 R160_Ch3.2@4987,5023.46
  Bottom Layer w15: v2(4881,5314.84) 4881,5390.84 U29_Ch3.4@4881.2,5391.05
3-COM_Ch4: R160_Ch4.2 U29_Ch4.4 | length 426.8
  Top Layer w12: v2(6443,5314.76) 6469,5314.76 6546,5237.76 v2(6546,5056.76)
  Bottom Layer w12: v2(6546,5056.76) 6546,5026.39 R160_Ch4.2@6549,5023.39
  Bottom Layer w15: v2(6443,5314.76) 6443,5390.76 U29_Ch4.4@6443.2,5390.97
3-COM_Ch5: R160_Ch5.2 U29_Ch5.4 | length 426.8
  Top Layer w12: v2(8398.7,5314.69) 8424.7,5314.69 8501.7,5237.69 v2(8501.7,5056.69)
  Bottom Layer w12: v2(8501.7,5056.69) 8501.7,5026.31 R160_Ch5.2@8504.7,5023.31
  Bottom Layer w15: v2(8398.7,5314.69) 8398.7,5390.69 U29_Ch5.4@8398.91,5390.89
3-COM_Ch6: R160_Ch6.2 U29_Ch6.4 | length 426.8
  Top Layer w12: v2(9960.7,5314.61) 9986.7,5314.61 10063.7,5237.61 v2(10063.7,5056.61)
  Bottom Layer w12: v2(10063.7,5056.61) 10063.7,5026.23 R160_Ch6.2@10066.7,5023.23
  Bottom Layer w15: v2(9960.7,5314.61) 9960.7,5390.61 U29_Ch6.4@9960.91,5390.81
3-COM_Ch7: R160_Ch7.2 U29_Ch7.4 | length 426.8
  Top Layer w12: v2(11522.7,5314.53) 11548.7,5314.53 11625.7,5237.53 v2(11625.7,5056.53)
  Bottom Layer w12: v2(11625.7,5056.53) 11625.7,5026.15 R160_Ch7.2@11628.7,5023.15
  Bottom Layer w15: v2(11522.7,5314.53) 11522.7,5390.53 U29_Ch7.4@11522.91,5390.73
3-COM_Ch8: R160_Ch8.2 U29_Ch8.4 | length 426.8
  Top Layer w12: v2(13084.7,5314.45) 13110.7,5314.45 13187.7,5237.45 v2(13187.7,5056.45)
  Bottom Layer w12: v2(13187.7,5056.45) 13187.7,5026.07 R160_Ch8.2@13190.7,5023.07
  Bottom Layer w15: v2(13084.7,5314.45) 13084.7,5390.45 U29_Ch8.4@13084.91,5390.65
5V: C44_Ch1.1 C44_Ch2.1 C44_Ch3.1 C44_Ch4.1 C44_Ch5.1 C44_Ch6.1 C44_Ch7.1 C44_Ch8.1 C150_Ch1.1 C150_Ch2.1 C150_Ch3.1 C150_Ch4.1 C150_Ch5.1 C150_Ch6.1 C150_Ch7.1 C150_Ch8.1 C167_Ch1.1 C167_Ch2.1 C167_Ch3.1 C167_Ch4.1 C167_Ch5.1 C167_Ch6.1 C167_Ch7.1 C167_Ch8.1 R61_Ch1.2 R61_Ch2.2 R61_Ch3.2 R61_Ch4.2 R61_Ch5.2 R61_Ch6.2 R61_Ch7.2 R61_Ch8.2 R159_Ch1.2 R159_Ch2.2 R159_Ch3.2 R159_Ch4.2 R159_Ch5.2 R159_Ch6.2 R159_Ch7.2 R159_Ch8.2 R182.1 R200.2 R201.1 R205.2 TP27.1 U9_Ch1.8 U9_Ch2.8 U9_Ch3.8 U9_Ch4.8 U9_Ch5.8 U9_Ch6.8 U9_Ch7.8 U9_Ch8.8 U30_Ch1.5 U30_Ch2.5 U30_Ch3.5 U30_Ch4.5 U30_Ch5.5 U30_Ch6.5 U30_Ch7.5 U30_Ch8.5 U32_Ch1.5 U32_Ch2.5 U32_Ch3.5 U32_Ch4.5 U32_Ch5.5 U32_Ch6.5 U32_Ch7.5 U32_Ch8.5 | length 3270.3
  Top Layer w20: U9_Ch1.8@1623.72,5698.55 1623.72,5631.91 C44_Ch1.1@1623.5,5631.7 1626.6,5628.6 v2(1626.6,5580.2) ; TP27.1@2226,7821 R182.1@2226,7710.56 R182.1@2227.56,7709 ; v1(2362,6731) R200.2@2362,6780.38 ; v2(3185.5,5580.12) C44_Ch2.1@3185.5,5631.62 3185.72,5631.83 U9_Ch2.8@3185.72,5698.47 ; v2(4747.5,5580.04) C44_Ch3.1@4747.5,5631.54 4747.72,5631.76 U9_Ch3.8@4747.72,5698.39 ; v2(6309.5,5579.96) C44_Ch4.1@6309.5,5631.46 6309.72,5631.68 U9_Ch4.8@6309.72,5698.31 ; v2(8265.2,5579.88) C44_Ch5.1@8265.2,5631.39 8265.42,5631.6 U9_Ch5.8@8265.42,5698.24 ; v2(9827.2,5579.8) C44_Ch6.1@9827.2,5631.31 9827.42,5631.52 U9_Ch6.8@9827.42,5698.16 ; U9_Ch7.8@11389.42,5698.08 11389.42,5631.44 C44_Ch7.1@11389.2,5631.23 11389.6,5630.83 v2(11389.6,5579.72) ; v2(12951.2,5579.65) C44_Ch8.1@12951.2,5631.15 12951.42,5631.36 U9_Ch8.8@12951.42,5698
  Bottom Layer w15: R159_Ch1.2@1573,5215 v2(1573,5251.44) ; R159_Ch2.2@3135,5214.92 v2(3135,5251.36) ; R159_Ch3.2@4697,5214.84 v2(4697,5251.28) ; R159_Ch4.2@6259,5214.76 v2(6259,5251.2) ; R159_Ch5.2@8214.7,5214.69 v2(8214.7,5251.13) ; R159_Ch6.2@9776.7,5214.61 v2(9776.7,5251.05) ; v2(11334,5250) 11338.7,5245.3 R159_Ch7.2@11338.7,5214.53 ; R159_Ch8.2@12900.7,5214.45 v2(12900.7,5250.89)
  Bottom Layer w20: v2(1665,4996) 1665.5,4995.5 C150_Ch1.1@1665.5,4976.08 1665.71,4975.87 U30_Ch1.5@1731.6,4975.87 ; v2(1751.28,5873.7) R61_Ch1.2@1790.38,5873.7 ; U32_Ch1.5@1830.13,6039.83 1900.66,6039.83 C167_Ch1.1@1902,6038.5 v2(1902,6074.02) ; v2(3227,4995.92) 3227.5,4995.43 3227.5,4976 C150_Ch2.1@3227.71,4975.79 U30_Ch2.5@3293.6,4975.79 ; v2(3313.28,5873.62) R61_Ch2.2@3352.38,5873.62 ; U32_Ch2.5@3392.38,6039.51 3462.91,6039.51 C167_Ch2.1@3464.24,6038.17 v2(3464.24,6073.69) ; v2(4789,4995.84) 4789.5,4995.35 4789.5,4975.92 C150_Ch3.1@4789.71,4975.71 U30_Ch3.5@4855.6,4975.71 ; v2(4875.28,5873.54) R61_Ch3.2@4914.38,5873.54 ; U32_Ch3.5@4952.49,6039.91 5023.01,6039.91 C167_Ch3.1@5024.35,6038.57 v2(5024.35,6074.09) ; v2(6351,4995.76) 6351.5,4995.27 6351.5,4975.84 6351.71,4975.63 U30_Ch4.5@6417.6,4975.63 ; v2(6437.28,5873.46) R61_Ch4.2@6476.38,5873.46 ; U32_Ch4.5@6516.38,6039.35 6586.91,6039.35 C167_Ch4.1@6588.24,6038.02 v2(6588.24,6073.54) ; v2(8306.7,4995.69) 8307.2,4995.19 8307.2,4975.76 8307.41,4975.55 U30_Ch5.5@8373.3,4975.55 ; v2(8392.98,5873.39) R61_Ch5.2@8432.08,5873.39 ; U32_Ch5.5@8472.08,6039.28 8542.61,6039.28 C167_Ch5.1@8543.94,6037.94 v2(8543.94,6073.46) ; v2(9868.7,4995.61) 9869.2,4995.11 C150_Ch6.1@9869.2,4975.69 9869.41,4975.47 U30_Ch6.5@9935.3,4975.47 ; v2(9954.98,5873.31) R61_Ch6.2@9994.08,5873.31 ; U32_Ch6.5@10034.83,6038.44 10105.36,6038.44 C167_Ch6.1@10106.7,6037.1 v2(10106.7,6072.62) ; v2(11430.7,4995.53) 11431.2,4995.03 11431.2,4975.61 C150_Ch7.1@11431.41,4975.39 U30_Ch7.5@11497.3,4975.39 ; v2(11516.98,5873.23) R61_Ch7.2@11556.08,5873.23 ; U32_Ch7.5@11596.08,6039.12 11666.61,6039.12 C167_Ch7.1@11667.94,6037.78 v2(11667.94,6073.3) ; v2(12992.7,4995.45) 12993.2,4994.95 C150_Ch8.1@12993.2,4975.53 12993.41,4975.32 U30_Ch8.5@13059.3,4975.32 ; v2(13078.98,5873.15) R61_Ch8.2@13118.08,5873.15 ; U32_Ch8.5@13158.08,6039.04 13228.61,6039.04 C167_Ch8.1@13229.94,6037.7 v2(13229.94,6073.22)
  other v1: 2299.49,7798.46 2326,7842 2283.86,7868
5V_D: J5.48 J5.84 J5.98 J5.112 J6.158 J6.180 R163.1 R176.2 R183.1 TP33.1 | length 8518.7
  Top Layer w20: R183.1@2425.44,8037 2426,8037.56 TP33.1@2426,8132 ; J5.48@6435.6,7676.48 J5.48@6435.67,7676.56 v2(6435.67,7784.48) ; v2(7128.28,7778.7) 7128.28,7676.86 J5.84@7128.58,7676.56 J5.84@7128.51,7676.48 ; J5.98@7348.98,7676.48 J5.98@7349.06,7676.56 7349.87,7675.74 7349.87,7798.37 7349,7799.25 v2(7349,7803) ; J5.112@7569.45,7676.48 J5.112@7569.53,7676.56 v2(7569.53,7784.48) ; J6.158@8889.14,7676.48 J6.158@8889.21,7676.56 v2(8889.21,7784.48) ; J6.180@9235.6,7676.48 J6.180@9235.67,7676.56 v2(9235.67,7784.48)
  Top Layer w40: TP33.1@2426,8132 2866.5,8132 R163.1@2895.5,8103
  Power Layer w20: v2(7128.28,7778.7) 7184.58,7835 7317,7835 v2(7349,7803) 7551.01,7803 v2(7569.53,7784.48) v2(8889.21,7784.48) v2(9235.67,7784.48)
  Power Layer w25: TP33.1@2426,8132 2500.31,8206.31 6286.69,8206.31 6357,8136 6357,7946.69 6435.67,7868.02 v2(6435.67,7784.48) 6510.16,7710 7059.58,7710 v2(7128.28,7778.7)
10V: C23_Ch1.1 C23_Ch2.1 C23_Ch3.1 C23_Ch4.1 C23_Ch5.1 C23_Ch6.1 C23_Ch7.1 C23_Ch8.1 C24_Ch1.1 C24_Ch2.1 C24_Ch3.1 C24_Ch4.1 C24_Ch5.1 C24_Ch6.1 C24_Ch7.1 C24_Ch8.1 C29_Ch1.1 C29_Ch2.1 C29_Ch3.1 C29_Ch4.1 C29_Ch5.1 C29_Ch6.1 C29_Ch7.1 C29_Ch8.1 C34_Ch1.1 C34_Ch2.1 C34_Ch3.1 C34_Ch4.1 C34_Ch5.1 C34_Ch6.1 C34_Ch7.1 C34_Ch8.1 C53_Ch1.1 C53_Ch2.1 C53_Ch3.1 C53_Ch4.1 C53_Ch5.1 C53_Ch6.1 C53_Ch7.1 C53_Ch8.1 C105.1 C121.1 C137.1 C140.1 L4.2 R190.2 R191.2 TP32.1 U3_Ch1.8 U3_Ch2.8 U3_Ch3.8 U3_Ch4.8 U3_Ch5.8 U3_Ch6.8 U3_Ch7.8 U3_Ch8.8 U5_Ch1.5 U5_Ch2.5 U5_Ch3.5 U5_Ch4.5 U5_Ch5.5 U5_Ch6.5 U5_Ch7.5 U5_Ch8.5 U6_Ch1.8 U6_Ch2.8 U6_Ch3.8 U6_Ch4.8 U6_Ch5.8 U6_Ch6.8 U6_Ch7.8 U6_Ch8.8 U10_Ch1.5 U10_Ch2.5 U10_Ch3.5 U10_Ch4.5 U10_Ch5.5 U10_Ch6.5 U10_Ch7.5 U10_Ch8.5 U22.4 U31.4 | length 33081
  Top Layer w20: v2(1714.84,5529.54) C24_Ch1.1@1762,5529.54 C23_Ch1.1@1826,5529.54 1882.94,5529.54 1897,5515.49 U3_Ch1.8@1897,5494.33 ; C53_Ch1.1@2803.94,5117.32 U10_Ch1.5@2803.94,5184.17 ; C53_Ch1.1@2804.09,5117.17 v2(2850.01,5117.17) ; v2(3324,5576.62) C24_Ch2.1@3324,5529.46 C23_Ch2.1@3388,5529.46 3444.94,5529.46 3459,5515.41 U3_Ch2.8@3459,5494.25 ; U10_Ch2.5@4365.94,5184.09 4365.94,5117.24 C53_Ch2.1@4366.09,5117.09 v2(4412.01,5117.09) ; v2(4886,5576.54) C24_Ch3.1@4886,5529.39 C23_Ch3.1@4950,5529.39 5006.94,5529.39 5021,5515.33 U3_Ch3.8@5021,5494.17 ; C53_Ch3.1@5927.94,5117.16 U10_Ch3.5@5927.94,5184.01 ; C53_Ch3.1@5928.09,5117.01 v2(5974.01,5117.01) ; v2(6448,5576.46) C24_Ch4.1@6448,5529.31 C23_Ch4.1@6512,5529.31 6568.94,5529.31 6583,5515.25 U3_Ch4.8@6583,5494.09 ; C53_Ch4.1@7489.94,5117.08 U10_Ch4.5@7489.94,5183.93 ; C53_Ch4.1@7490.09,5116.93 v2(7536.01,5116.93) ; v2(8403.7,5576.39) C24_Ch5.1@8403.7,5529.23 C23_Ch5.1@8467.7,5529.23 8524.65,5529.23 8538.7,5515.17 U3_Ch5.8@8538.7,5494.02 ; C53_Ch5.1@9445.65,5117 U10_Ch5.5@9445.65,5183.85 ; C53_Ch5.1@9445.79,5116.85 v2(9491.71,5116.85) ; v2(9965.7,5576.31) C24_Ch6.1@9965.7,5529.15 C23_Ch6.1@10029.7,5529.15 10086.65,5529.15 10100.7,5515.09 U3_Ch6.8@10100.7,5493.94 ; C53_Ch6.1@11007.65,5116.92 U10_Ch6.5@11007.65,5183.77 ; C53_Ch6.1@11007.79,5116.77 v2(11053.71,5116.77) ; v2(11527.7,5576.23) C24_Ch7.1@11527.7,5529.07 C23_Ch7.1@11591.7,5529.07 11648.65,5529.07 11662.7,5515.02 U3_Ch7.8@11662.7,5493.86 ; C53_Ch7.1@12569.65,5116.84 U10_Ch7.5@12569.65,5183.69 ; C53_Ch7.1@12569.79,5116.69 v2(12615.71,5116.69) ; v2(13089.7,5576.15) C24_Ch8.1@13089.7,5528.99 C23_Ch8.1@13153.7,5528.99 13210.65,5528.99 13224.7,5514.94 U3_Ch8.8@13224.7,5493.78 ; C53_Ch8.1@14131.65,5116.76 U10_Ch8.5@14131.65,5183.61 ; C53_Ch8.1@14131.79,5116.62 v2(14177.71,5116.62)
  Power Layer w20: v2(2075.79,5205.7) 2125.49,5156 2811.17,5156 v2(2850.01,5117.17) 2879.31,5146.47 3578.64,5146.47 v2(3637.79,5205.62) 3687.41,5156 4373.09,5156 v2(4412.01,5117.09) 4441.31,5146.39 5140.64,5146.39 v2(5199.79,5205.54) 5248.33,5157 5934.02,5157 v2(5974.01,5117.01) 6003.31,5146.31 6702.64,5146.31 v2(6761.79,5205.46) 6801.25,5166 7486.94,5166 v2(7536.01,5116.93) 7565.31,5146.24 8658.34,5146.24 v2(8717.49,5205.39) 8758.87,5164 9444.56,5164 v2(9491.71,5116.85) 9521.01,5146.16 10220.34,5146.16 v2(10279.49,5205.31) 10328.8,5156 11014.48,5156 v2(11053.71,5116.77) 11083.01,5146.08 11782.34,5146.08 v2(11841.49,5205.23) 11886.72,5160 12572.4,5160 v2(12615.71,5116.69) 12645.01,5146 13344.34,5146 v2(13403.49,5205.15) 13445.64,5163 14131.32,5163 v2(14177.71,5116.62)
  Power Layer w25: TP32.1@1510.2,7136.69 1333,6959.49 1333,5270 1461,5142 2012.09,5142 v2(2075.79,5205.7)
  Signal Layer 2 w20: v2(1714.84,5529.54) 1976.54,5529.54 1993.92,5546.92 2035,5546.92 ; 2050.53,5531.4 2035,5546.92 ; 2050.53,5562.45 2035,5546.92 ; v2(2075.79,5205.7) 2050.53,5230.96 2050.53,5546.92 ; v2(2323.85,6063.34) 2323.43,6063.34 2050.53,5790.44 2050.53,5546.92 ; v2(3324,5576.62) 3371.16,5529.46 3544.15,5529.46 3561.53,5546.84 3594,5546.84 ; 3612.53,5528.32 3594,5546.84 ; 3612.53,5565.37 3594,5546.84 ; v2(3637.79,5205.62) 3612.53,5230.88 3612.53,5546.84 3612.53,5790.36 3885.43,6063.26 v2(3885.85,6063.26) ; v2(4886,5576.54) 4938.54,5524 5069,5524 5091.76,5546.76 5155,5546.76 ; 5174.53,5527.24 5155,5546.76 ; 5174.53,5566.29 5155,5546.76 ; v2(5199.79,5205.54) 5174.53,5230.81 5174.53,5546.76 5174.53,5790.28 5447.43,6063.18 v2(5447.85,6063.18) ; v2(6448,5576.46) 6495.16,5529.31 6660.31,5529.31 6677.69,5546.69 6721,5546.69 ; 6736.53,5531.16 6721,5546.69 ; 6736.53,5562.21 6721,5546.69 ; v2(6761.79,5205.46) 6736.53,5230.73 6736.53,5546.69 6736.53,5790.2 7009.43,6063.1 v2(7009.85,6063.1) ; v2(8403.7,5576.39) 8455.09,5525 8596,5525 8617.61,5546.61 8677,5546.61 ; 8692.23,5531.38 8677,5546.61 ; 8692.23,5561.83 8677,5546.61 ; v2(8717.49,5205.39) 8692.23,5230.65 8692.23,5546.61 8692.23,5790.12 8965.13,6063.02 v2(8965.55,6063.02) ; v2(9965.7,5576.31) 10019.01,5523 10170,5523 10193.53,5546.53 10236,5546.53 ; 10254.23,5528.3 10236,5546.53 ; 10254.23,5564.75 10236,5546.53 ; v2(10279.49,5205.31) 10254.23,5230.57 10254.23,5546.53 10254.23,5790.05 10527.13,6062.94 v2(10527.55,6062.94) ; v2(11527.7,5576.23) 11577.93,5526 11729.69,5526 11750.14,5546.45 11795,5546.45 ; 11816.23,5525.22 11795,5546.45 ; 11816.23,5567.68 11795,5546.45 ; v2(11841.49,5205.23) 11816.23,5230.49 11816.23,5546.45 11816.23,5789.97 12089.13,6062.87 v2(12089.55,6062.87) ; v2(13089.7,5576.15) 13144.85,5521 13255,5521 13280.37,5546.37 13360,5546.37 ; 13378.23,5528.14 13360,5546.37 ; 13378.23,5564.6 13360,5546.37 ; v2(13403.49,5205.15) 13378.23,5230.41 13378.23,5546.37 13378.23,5789.89 13651.13,6062.79 v2(13651.55,6062.79) ; 2035,5546.92 2050.53,5546.92
  Bottom Layer w20: v1(1798.93,7628) 1821.93,7605 1879.5,7605 R190.2@1888.5,7614 ; R191.2@1982,8075.5 1982,8181 2008,8207 v1(2048,8207) ; U5_Ch1.5@1997.6,5340.91 1997.6,5268.14 C29_Ch1.1@1997.5,5268.05 1997.5,5219.98 2011.79,5205.7 v2(2075.79,5205.7) ; U6_Ch1.8@2208,6063.33 C34_Ch1.1@2277.78,6063.33 ; C34_Ch1.1@2278.21,6063.34 v2(2323.85,6063.34) ; U5_Ch2.5@3559.6,5340.83 3559.6,5268.06 C29_Ch2.1@3559.5,5267.97 3559.5,5219.91 3573.79,5205.62 v2(3637.79,5205.62) ; U6_Ch2.8@3770,6063.25 C34_Ch2.1@3839.78,6063.25 ; C34_Ch2.1@3840.21,6063.26 v2(3885.85,6063.26) ; U5_Ch3.5@5121.6,5340.76 5121.6,5267.98 C29_Ch3.1@5121.5,5267.89 5121.5,5219.83 5135.79,5205.54 v2(5199.79,5205.54) ; U6_Ch3.8@5332,6063.17 C34_Ch3.1@5401.78,6063.17 ; C34_Ch3.1@5402.21,6063.18 v2(5447.85,6063.18) ; U5_Ch4.5@6683.6,5340.68 6683.6,5267.91 C29_Ch4.1@6683.5,5267.81 6683.5,5219.75 6697.79,5205.46 v2(6761.79,5205.46) ; U6_Ch4.8@6894,6063.09 C34_Ch4.1@6963.78,6063.09 ; C34_Ch4.1@6964.21,6063.1 v2(7009.85,6063.1) ; U5_Ch5.5@8639.3,5340.6 8639.3,5267.83 C29_Ch5.1@8639.2,5267.73 8639.2,5219.67 8653.49,5205.39 v2(8717.49,5205.39) ; U6_Ch5.8@8849.7,6063.02 C34_Ch5.1@8919.48,6063.02 ; C34_Ch5.1@8919.91,6063.02 v2(8965.55,6063.02) ; U5_Ch6.5@10201.3,5340.52 10201.3,5267.75 C29_Ch6.1@10201.2,5267.65 10201.2,5219.59 10215.49,5205.31 v2(10279.49,5205.31) ; U6_Ch6.8@10411.7,6062.94 C34_Ch6.1@10481.48,6062.94 ; C34_Ch6.1@10481.91,6062.94 v2(10527.55,6062.94) ; U5_Ch7.5@11763.3,5340.44 11763.3,5267.67 C29_Ch7.1@11763.2,5267.57 11763.2,5219.51 11777.49,5205.23 v2(11841.49,5205.23) ; U6_Ch7.8@11973.7,6062.86 C34_Ch7.1@12043.48,6062.86 ; C34_Ch7.1@12043.91,6062.87 v2(12089.55,6062.87) ; U5_Ch8.5@13325.3,5340.36 13325.3,5267.59 C29_Ch8.1@13325.2,5267.5 13325.2,5219.43 13339.49,5205.15 v2(13403.49,5205.15) ; U6_Ch8.8@13535.7,6062.78 C34_Ch8.1@13605.48,6062.78 ; C34_Ch8.1@13605.91,6062.79 v2(13651.55,6062.79)
  Bottom Layer w25: TP32.1@1510.2,7136.69 1692.51,7319 2030,7319 2110,7399 2110,8145 v1(2081,8174) v1(2048,8207)
10V_Gate: C113.1 C114.1 D9.1 L4.1 R8_Ch1.2 R8_Ch2.2 R8_Ch3.2 R8_Ch4.2 R8_Ch5.2 R8_Ch6.2 R8_Ch7.2 R8_Ch8.2 R209.1 R215.2 TP29.1 U23.10 | length 26712.7
  Top Layer w20: D9.1@951,7774.7 951.56,7775.26 R209.1@951.56,7938.7 ; v2(2012.11,3840.11) 2012.11,3799.1 R8_Ch1.2@2012.39,3798.82 ; v2(3574.11,3840.04) 3574.11,3799.02 R8_Ch2.2@3574.39,3798.74 ; v2(5136.11,3839.96) 5136.11,3798.94 R8_Ch3.2@5136.39,3798.66 ; v2(6698.11,3839.88) 6698.11,3798.86 R8_Ch4.2@6698.39,3798.58 ; v2(8653.81,3839.8) 8653.81,3798.78 R8_Ch5.2@8654.09,3798.5 ; v2(10215.81,3839.72) 10215.81,3798.7 R8_Ch6.2@10216.09,3798.42 ; v2(11777.81,3839.64) 11777.81,3798.63 R8_Ch7.2@11778.09,3798.34 ; v2(13339.81,3839.56) 13339.81,3798.55 R8_Ch8.2@13340.09,3798.27
  Power Layer w20: v2(2374,4971) 2431,4914 3877,4914 v2(3934,4971) 3991,4914 5449.04,4914 v2(5506.04,4971) 5563.04,4914 6996,4914 v2(7069,4987) 7145,4911 8952,4911 v2(9028,4987) 9101.86,4913.14 10512.14,4913.14 v2(10586,4987) 10661,4912 12073,4912 v2(12148,4987) 12223,4912 13634.74,4912 v2(13709.74,4987)
  Power Layer w25: v1(1086.51,6658.7) v1(1086.51,6612.19) 1086.51,5020.49 1193,4914 2317,4914 v2(2374,4971)
  Signal Layer 2 w25: v2(2012.11,3840.11) 2033,3861 2033,4830 2174,4971 v2(2374,4971) ; v2(3574.11,3840.04) 3595,3860.92 3595,4835 3731,4971 v2(3934,4971) ; v2(5136.11,3839.96) 5157,3860.84 5157,4853 5275,4971 v2(5506.04,4971) ; v2(6698.11,3839.88) 6719,3860.77 6719,4854 6852,4987 v2(7069,4987) ; v2(8653.81,3839.8) 8674.7,3860.69 8674.7,4913.7 8748,4987 v2(9028,4987) ; v2(10215.81,3839.72) 10236.7,3860.61 10236.7,4910 10313.7,4987 v2(10586,4987) ; v2(11777.81,3839.64) 11798.7,3860.53 11798.7,4913.7 11872,4987 v2(12148,4987) ; v2(13339.81,3839.56) 13360.7,3860.45 13360.7,4907 13440.7,4987 v2(13709.74,4987)
12V_IN: C109.1 C110.1 C111.1 C157.1 C158.1 J4.1 L5.1 Q5.5 Q5.6 Q5.7 Q5.8 Q5.9 S3.1 TP28.1 U23.1 | length 349.9
  Top Layer w10: 714,6606.7 726.35,6619.05 U23.1@726.35,6657.5
  Top Layer w20: J4.1@143,6482 431.8,6482 TP28.1@435.5,6485.7
  other v4: 386.5,6650.7 426.5,6650.7 466.5,6650.7 506.5,6650.7 386.5,6690.7 426.5,6690.7 466.5,6690.7 506.5,6690.7 386.5,6730.7 426.5,6730.7 466.5,6730.7 506.5,6730.7
12V_Out: L1_Ch1.1 L1_Ch2.1 L1_Ch3.1 L1_Ch4.1 L1_Ch5.1 L1_Ch6.1 L1_Ch7.1 L1_Ch8.1 Q2.5 Q2.6 Q2.7 Q2.8 Q2.9@868.46,1878 R83.2 S3.2 TP4_Ch1.1 TP4_Ch2.1 TP4_Ch3.1 TP4_Ch4.1 TP4_Ch5.1 TP4_Ch6.1 TP4_Ch7.1 TP4_Ch8.1
  other v1: 1051.25,1736 981.25,1806 1051.25,1806 981.25,1876 1051.25,1876 981.25,1946 1051.25,1946 841.25,2016 911.25,2016 981.25,2016 1051.25,2016 771.25,2086 911.25,2086 1051.25,2086 631.25,2156 771.25,2156 911.25,2156 1051.25,2156 631.25,2296 771.25,2296 911.25,2296 1051.25,2296 631.25,2436 771.25,2436 911.25,2436 1051.25,2436 631.25,2576 771.25,2576 911.25,2576 1051.25,2576 631.25,2716 771.25,2716 911.25,2716 1051.25,2716 631.25,2856 771.25,2856 911.25,2856 1051.25,2856 631.25,2996 771.25,2996 911.25,2996 1051.25,2996 631.25,3136 771.25,3136 911.25,3136 1051.25,3136 631.25,3276 771.25,3276 911.25,3276 1051.25,3276 631.25,3416 771.25,3416 911.25,3416 1051.25,3416 631.25,3556 771.25,3556 911.25,3556 1051.25,3556 631.25,3696 771.25,3696 911.25,3696 1051.25,3696 631.25,3836 771.25,3836 911.25,3836 1051.25,3836 631.25,3976 771.25,3976 911.25,3976 1051.25,3976 631.25,4116 771.25,4116 911.25,4116 1051.25,4116 9949.7,4117.61 10019.7,4117.61 10089.7,4117.61 11511.7,4117.53 11581.7,4117.53 11651.7,4117.53 13073.7,4117.45 13143.7,4117.45 13213.7,4117.45 1746,4118 1816,4118 1886,4118 3308,4117.92 3378,4117.92 3448,4117.92 4870,4117.84 4940,4117.84 5010,4117.84 6432,4117.76 6502,4117.76 6572,4117.76 8387.7,4117.69 8457.7,4117.69 8527.7,4117.69 9949.7,4187.61 11511.7,4187.53 13073.7,4187.45 1746,4188 3308,4187.92 4870,4187.84 6432,4187.76 8387.7,4187.69 631.25,4256 771.25,4256 911.25,4256 1051.25,4256 9949.7,4257.61 10019.7,4257.61 10089.7,4257.61 11511.7,4257.53 11581.7,4257.53 11651.7,4257.53 13073.7,4257.45 13143.7,4257.45 13213.7,4257.45 1746,4258 1816,4258 1886,4258 3308,4257.92 3378,4257.92 3448,4257.92 4870,4257.84 4940,4257.84 5010,4257.84 6432,4257.76 6502,4257.76 6572,4257.76 8387.7,4257.69 8457.7,4257.69 8527.7,4257.69 9949.7,4327.61 10019.7,4327.61 10089.7,4327.61 11511.7,4327.53 11581.7,4327.53 11651.7,4327.53 13073.7,4327.45 13143.7,4327.45 13213.7,4327.45 1746,4328 1816,4328 1886,4328 3308,4327.92 3378,4327.92 3448,4327.92 4870,4327.84 4940,4327.84 5010,4327.84 6432,4327.76 6502,4327.76 6572,4327.76 8387.7,4327.69 8457.7,4327.69 8527.7,4327.69 631.25,4396 771.25,4396 911.25,4396 1051.25,4396 9949.7,4397.61 10019.7,4397.61 10089.7,4397.61 11511.7,4397.53 11581.7,4397.53 11651.7,4397.53 13073.7,4397.45 13143.7,4397.45 13213.7,4397.45 1746,4398 1816,4398 1886,4398 3308,4397.92 3378,4397.92 3448,4397.92 4870,4397.84 4940,4397.84 5010,4397.84 6432,4397.76 6502,4397.76 6572,4397.76 8387.7,4397.69 8457.7,4397.69 8527.7,4397.69 9949.7,4467.61 10019.7,4467.61 10089.7,4467.61 11511.7,4467.53 11581.7,4467.53 11651.7,4467.53 13073.7,4467.45 13143.7,4467.45 13213.7,4467.45 1746,4468 1816,4468 1886,4468 3308,4467.92 3378,4467.92 3448,4467.92 4870,4467.84 4940,4467.84 5010,4467.84 6432,4467.76 6502,4467.76 6572,4467.76 8387.7,4467.69 8457.7,4467.69 8527.7,4467.69 631.25,4536 771.25,4536 911.25,4536 1051.25,4536 9949.7,4537.61 10019.7,4537.61 10089.7,4537.61 11511.7,4537.53 11581.7,4537.53 11651.7,4537.53 13073.7,4537.45 13143.7,4537.45 13213.7,4537.45 1746,4538 1816,4538 1886,4538 3308,4537.92 3378,4537.92 3448,4537.92 4870,4537.84 4940,4537.84 5010,4537.84 6432,4537.76 6502,4537.76 6572,4537.76 8387.7,4537.69 8457.7,4537.69 8527.7,4537.69 9949.7,4607.61 10019.7,4607.61 10089.7,4607.61 11511.7,4607.53 11581.7,4607.53 11651.7,4607.53 13073.7,4607.45 13143.7,4607.45 13213.7,4607.45 1746,4608 1816,4608 1886,4608 3308,4607.92 3378,4607.92 3448,4607.92 4870,4607.84 4940,4607.84 5010,4607.84 6432,4607.76 6502,4607.76 6572,4607.76 8387.7,4607.69 8457.7,4607.69 8527.7,4607.69 631.25,4676 771.25,4676 911.25,4676 1051.25,4676 9949.7,4677.61 10019.7,4677.61 10089.7,4677.61 11511.7,4677.53 11581.7,4677.53 11651.7,4677.53 13073.7,4677.45 13143.7,4677.45 13213.7,4677.45 1746,4678 1816,4678 1886,4678 3308,4677.92 3378,4677.92 3448,4677.92 4870,4677.84 4940,4677.84 5010,4677.84 6432,4677.76 6502,4677.76 6572,4677.76 8387.7,4677.69 8457.7,4677.69 8527.7,4677.69 9949.7,4747.61 10019.7,4747.61 10089.7,4747.61 11511.7,4747.53 11581.7,4747.53 11651.7,4747.53 13073.7,4747.45 13143.7,4747.45 13213.7,4747.45 1746,4748 1816,4748 1886,4748 3308,4747.92 3378,4747.92 3448,4747.92 4870,4747.84 4940,4747.84 5010,4747.84 6432,4747.76 6502,4747.76 6572,4747.76 8387.7,4747.69 8457.7,4747.69 8527.7,4747.69 631.25,4816 771.25,4816 911.25,4816 1051.25,4816 9949.7,4817.61 10019.7,4817.61 10089.7,4817.61 11511.7,4817.53 11581.7,4817.53 11651.7,4817.53 13073.7,4817.45 13143.7,4817.45 13213.7,4817.45 1746,4818 1816,4818 1886,4818 3308,4817.92 3378,4817.92 3448,4817.92 4870,4817.84 4940,4817.84 5010,4817.84 6432,4817.76 6502,4817.76 6572,4817.76 8387.7,4817.69 8457.7,4817.69 8527.7,4817.69
12VP: D7.2 D8.1 Q3.5 Q3.6 Q3.7 Q3.8 Q3.9@686.33,1312.02 R82.1 R84.2 R85.2 T1.1 | length 457.2
  Top Layer w20: D8.1@908.74,1081.82 912.04,1085.11 R85.2@912.04,1214.2 ; v1(1058.33,1178) R84.2@1058.33,1214.2
  Bottom Layer w20: v1(818,1208) 915.62,1208 935.62,1228 1039,1228 1058.33,1208.67 v1(1058.33,1178)
  other v1: 398,88 468,88 398,158 468,158 398,228 468,228 398,298 468,298 398,368 468,368 398,438 468,438 398,508 468,508 398,578 468,578 398,648 468,648 538,648 608,648 678,648 748,648 818,648 888,648 398,718 468,718 538,718 608,718 678,718 748,718 818,718 888,718 398,788 468,788 538,788 608,788 678,788 748,788 818,788 888,788 398,858 468,858 538,858 608,858 678,858 748,858 818,858 888,858 398,928 468,928 538,928 608,928 678,928 748,928 818,928 398,998 468,998 538,998 608,998 678,998 748,998 818,998 398,1068 468,1068 538,1068 608,1068 678,1068 748,1068 818,1068 398,1138 468,1138 538,1138 608,1138 678,1138 748,1138 818,1138 398,1208 468,1208 538,1208 608,1208 678,1208 748,1208 398,1278 468,1278 538,1278 818,1278 398,1348 468,1348 538,1348
  other v3: 539.33,67.56 584.33,67.56 629.33,67.56 674.33,67.56 719.33,67.56 764.33,67.56 809.33,67.56 854.33,67.56 539.33,112.56 584.33,112.56 629.33,112.56 674.33,112.56 719.33,112.56 764.33,112.56 809.33,112.56 854.33,112.56 539.33,157.56 584.33,157.56 809.33,157.56 854.33,157.56 539.33,202.56 854.33,202.56 539.33,522.56 854.33,522.56 539.33,567.56 584.33,567.56 809.33,567.56 854.33,567.56
+VSense_Ch1: J2_Ch1.1 R14_Ch1.2 | length 166.4
  Top Layer w15: J2_Ch1.1@1766,1182.79 1802.71,1219.5 1899.51,1219.5 R14_Ch1.2@1912.01,1207
+VSense_Ch2: J2_Ch2.1 R14_Ch2.2 | length 166.4
  Top Layer w15: J2_Ch2.1@3328,1182.71 3364.71,1219.42 3461.51,1219.42 R14_Ch2.2@3474.01,1206.92
+VSense_Ch3: J2_Ch3.1 R14_Ch3.2 | length 166.4
  Top Layer w15: J2_Ch3.1@4890,1182.63 4926.71,1219.34 5023.51,1219.34 R14_Ch3.2@5036.01,1206.84
+VSense_Ch4: J2_Ch4.1 R14_Ch4.2 | length 166.4
  Top Layer w15: J2_Ch4.1@6452,1182.55 6488.71,1219.26 6585.51,1219.26 R14_Ch4.2@6598.01,1206.76
+VSense_Ch5: J2_Ch5.1 R14_Ch5.2 | length 166.4
  Top Layer w15: J2_Ch5.1@8407.7,1182.47 8444.41,1219.19 8541.21,1219.19 R14_Ch5.2@8553.71,1206.69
